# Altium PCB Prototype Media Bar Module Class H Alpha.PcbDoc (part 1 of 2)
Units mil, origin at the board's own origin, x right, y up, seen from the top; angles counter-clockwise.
Board outline 436.13 x 1831.8 mil, 6 copper layers (Component Side, Ground Plane (GND), Inner Layer 1, Inner Layer 2, Power Plane (VCC), Solder Side), stack 51.068 mil thick; 139 components, 72 nets, 710 pads, 418 vias.
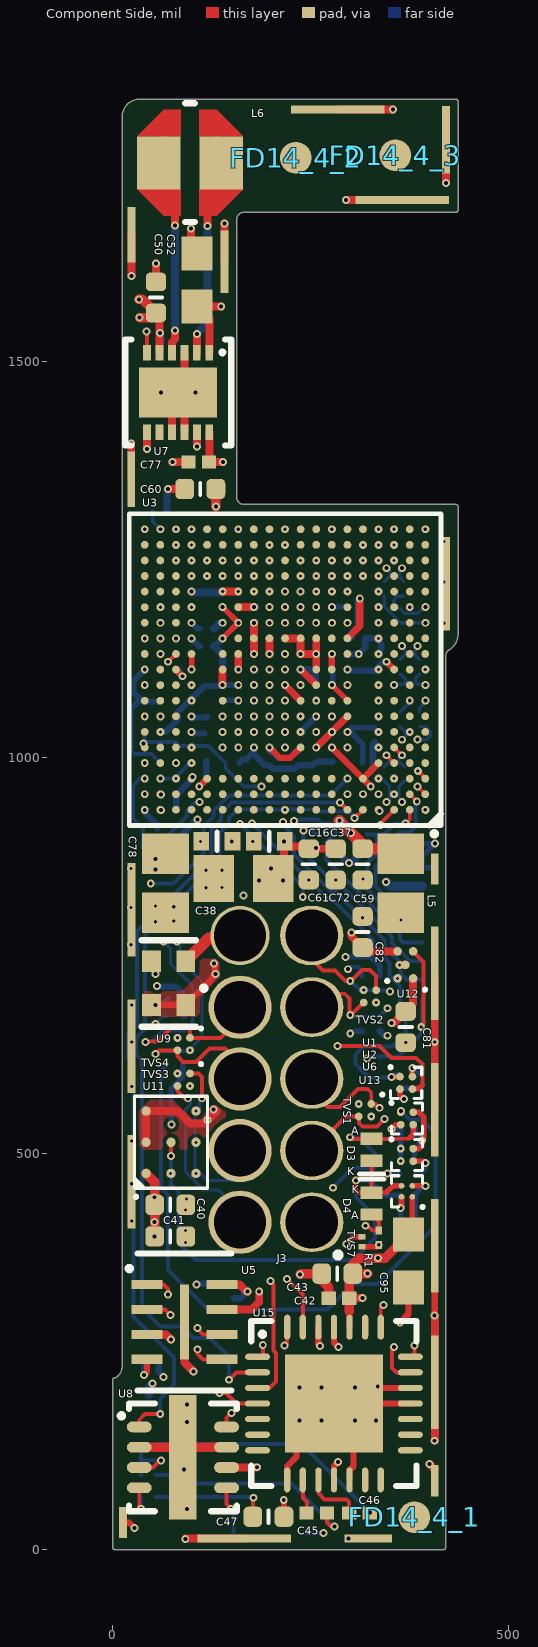
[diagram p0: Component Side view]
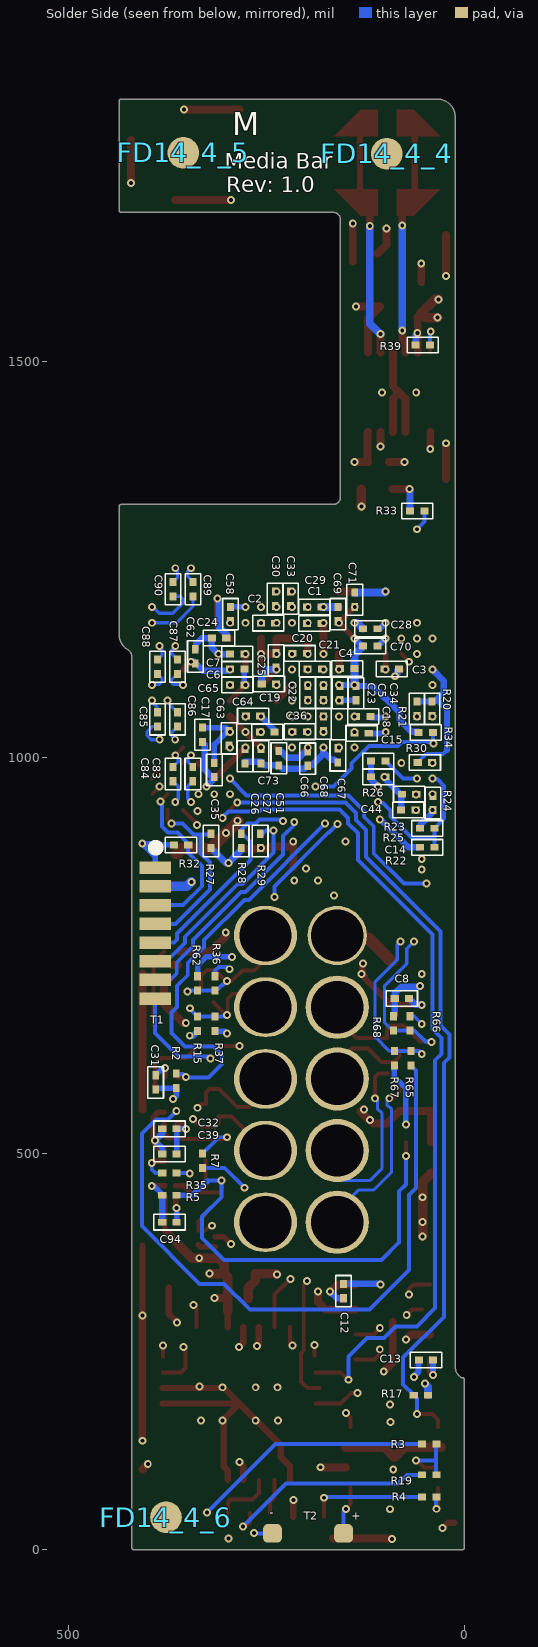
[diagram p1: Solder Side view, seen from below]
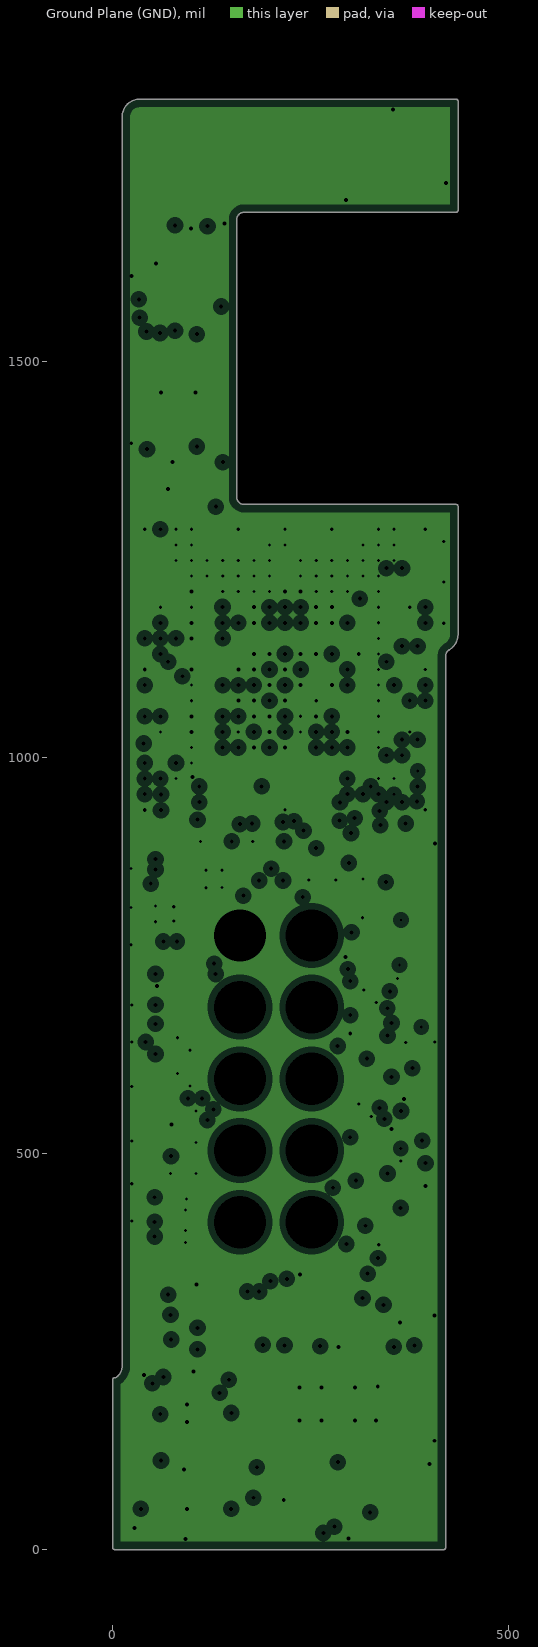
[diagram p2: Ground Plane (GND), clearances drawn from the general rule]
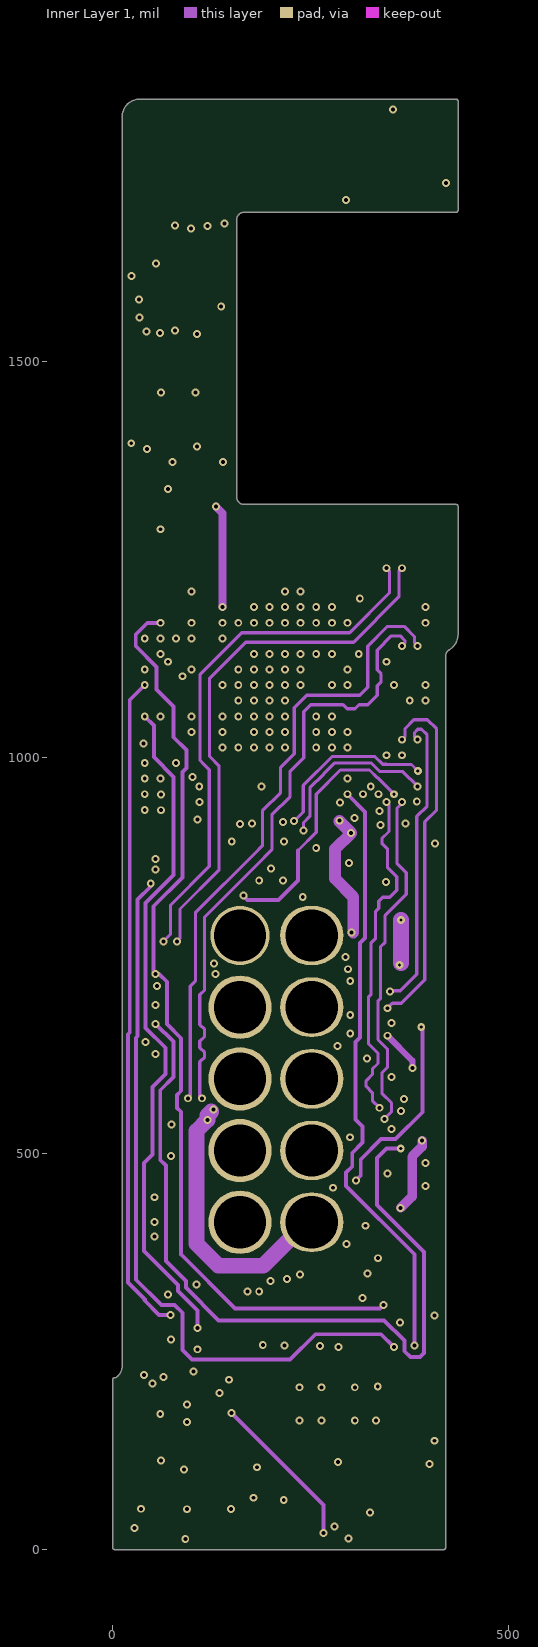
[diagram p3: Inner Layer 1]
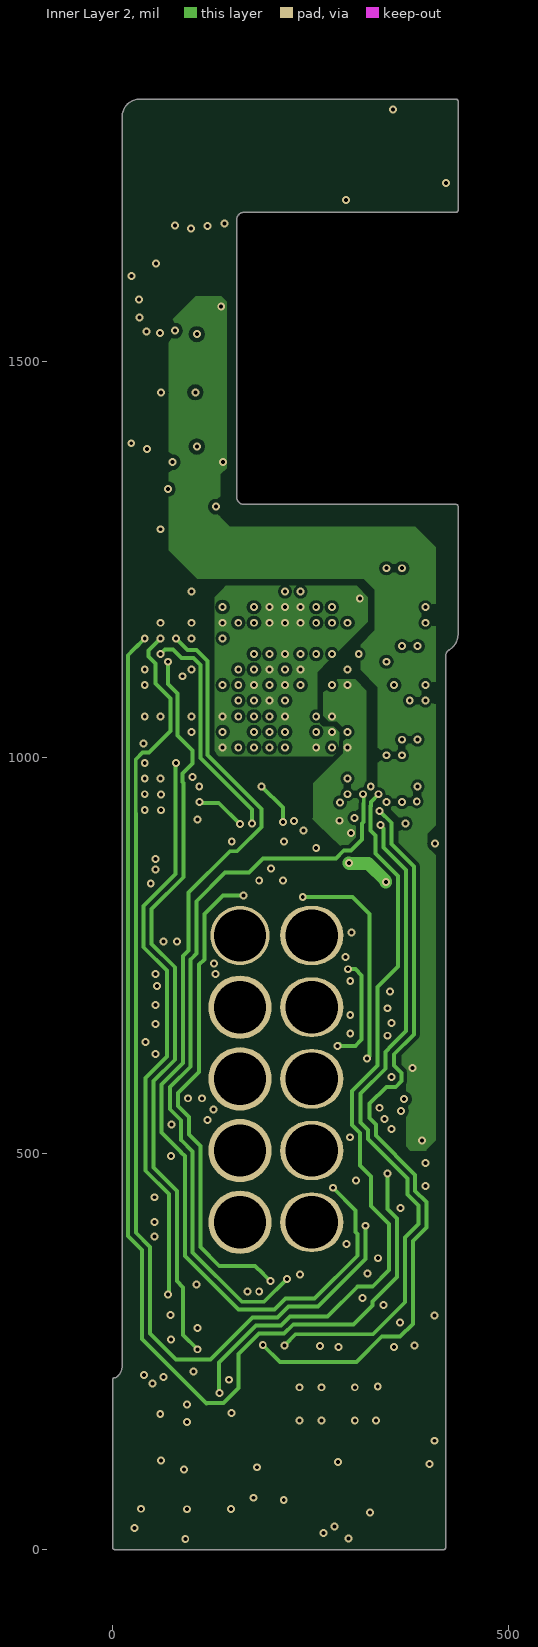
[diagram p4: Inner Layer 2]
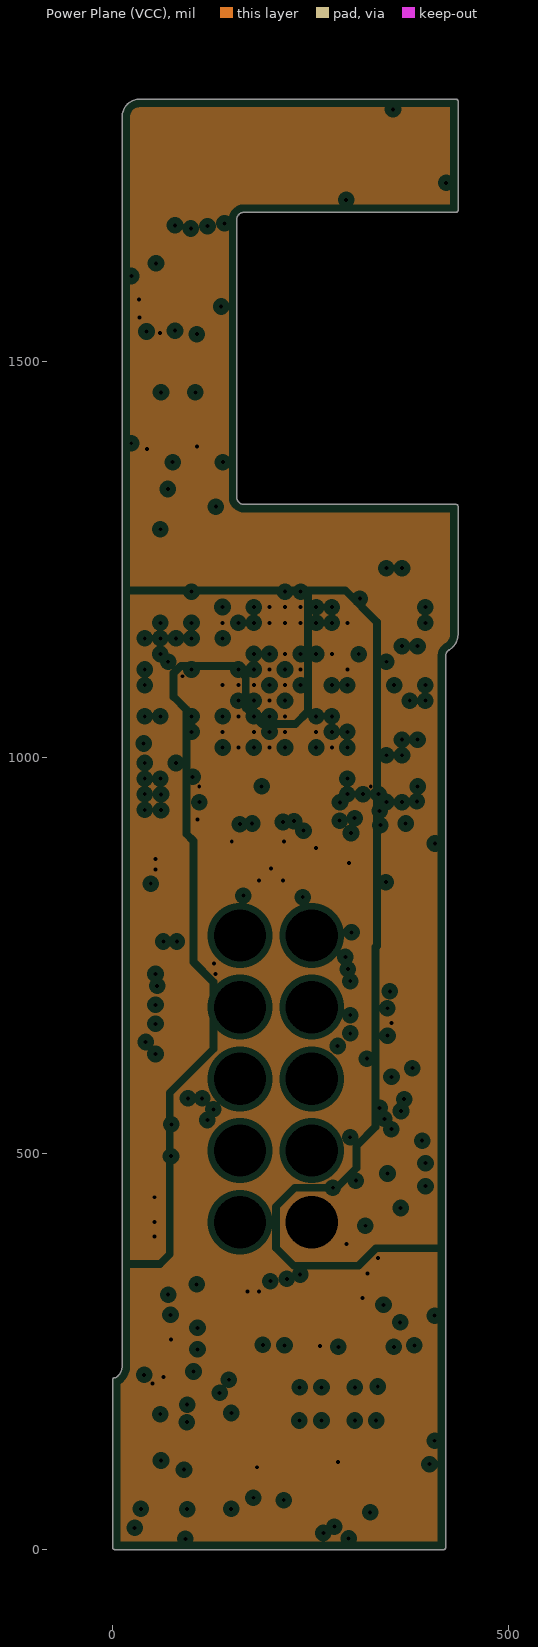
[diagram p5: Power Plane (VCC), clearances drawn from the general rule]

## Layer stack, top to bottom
Top Solder: solder mask 0.4, Solder Resist, Dk 3.5
Component Side: signal copper 1.4
Dielectric1: core 12.6, FR-4, Dk 4.8
Ground Plane (GND): plane copper 1.417, net GND
Dielectric4: prepreg 5, Dk 4.2
Inner Layer 1: signal copper 1.417
Dielectric2: core 10, Dk 4.2
Inner Layer 2: signal copper 1.417
Dielectric3: prepreg 5, Dk 4.2
Power Plane (VCC): plane copper 1.417, net (Multiple Nets)
Dielectric5: core 10, Dk 4.2
Solder Side: signal copper 1.4
Bottom Solder: solder mask 0.4, Solder Resist, Dk 3.5

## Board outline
0,2.51 ccw(c2.51,2.51) 2.51,0 417.87,0 ccw(c417.87,2.51) 420.38,2.51 420.38,1128.38 cw(c429.68,1128.38) 425.03,1136.44 ccw(c413.93,1155.66) 436.13,1155.66 436.13,1317.48 ccw(c433.62,1317.48) 433.62,1319.99 165.9,1319.99 cw(c165.9,1329.29) 156.6,1329.29 156.6,1679.68 cw(c165.9,1679.68) 165.9,1688.98 ccw(c165.9,1691.49) 165.92,1688.98 433.62,1688.98 ccw(c433.62,1691.49) 436.13,1691.49 436.13,1829.29 ccw(c433.62,1829.29) 433.62,1831.8 34.01,1831.8 cw(c34.01,1829.29) 34.03,1831.8 34.01,1831.8 ccw(c34.01,1809.6) 11.81,1809.6 11.81,231.63 cw(c-5.36,231.63) 3.47,216.91 ccw(c2.51,214.59) 0,214.59

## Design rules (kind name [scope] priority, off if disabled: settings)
Clearance Clearance_1 [withinroom(U3)] p1: gap=3.9
Clearance diff_1 [InNetClass('diff')] p2: gap=5
Clearance [All] p3: gap=5
DiffPairsRouting [All] p1: maxlimit=8 minlimit=8 mostfreqgap=8 toplayer_minwidth=15 toplayer_maxwidth=15 toplayer_prefwidth=15 midlayer1_minwidth=15 midlayer1_maxwidth=15 midlayer1_prefwidth=15 midlayer2_minwidth=15 midlayer2_maxwidth=15 midlayer2_prefwidth=15 bottomlayer_minwidth=15 bottomlayer_maxwidth=15 bottomlayer_prefwidth=15 maxuncoupledlength=500
FabricationTestPointUsage [All] p1 off: valid=0 allowmultiple=FALSE
FabricationTestpoint [(IsPad And (OnTopLayer Or OnBottomLayer))] p1 off: side=3 testpointundercomponent=TRUE minsize=40 maxsize=100 preferedsize=60 minholesize=0 maxholesize=40 preferedholesize=32 testpointgrid=1 allowsidetop=TRUE allowsidebottom=TRUE usegrid=TRUE gridtolerance=0.01
HoleToHoleClearance [All] p1: gap=3.9 allowstackedmicrovias=TRUE
MinimumSolderMaskSliver [All] p1: minsoldermaskwidth=3
PlaneClearance [All] p1: clearance=8
PlaneConnect [All] p1: planeconnectstyle=Direct reliefexpansion=8 reliefentries=4 reliefconductorwidth=8 reliefairgap=8
PolygonConnect [All] p1: connectstyle=Direct reliefconductorwidth=10 reliefentries=4 polygonreliefangle="90 Angle" airgapwidth=10
RoomDefinition U3 [InComponentClass('Components Class 1')] p1: confinementstyle=ConfineIn formatcopy=TRUE lockcomponents=FALSE outline 19,1308 411,1308 411,914 19,914
RoutingVias RoutingVias_1 [All] p1: holewidth=5 width=10 viastyle="Through Hole" minholewidth=4 minwidth=10 maxholewidth=6 maxwidth=12
SilkToSilkClearance [All] p1: silktosilkclearance=3
SilkToSolderMaskClearance [IsPad] p1: minsilkscreentomaskgap=3 clearancetoexposedcopper=TRUE
SolderMaskExpansion [All] p1: expansion=4
Width DiffPair_Width [InAnyDifferentialPair] p1: maxlimit=5 minlimit=4 preferedwidth=4
Width [All] p2: maxlimit=30 minlimit=4 preferedwidth=5
20 further rules are at their usual default settings.

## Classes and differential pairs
component class "Components Class 1": C1 C2 C3 C4 C5 C6 C7 C15 C17 C18 C19 C20 C21 C22 C23 C24 C25 C26 C27 C28 C29 C30 C33 C34 C35 C36 C44 C51 C58 C62 C63 C64 C65 C66 C67 C68 C69 C70 C71 C73 C83 C84 C85 C86 C87 C88 C89 C90 R20 R21 R23 R24 R25 R26 R28 R30 R32 R34
differential pair C_RX_CLK: +C_RX_CLK_P -C_RX_CLK_N
differential pair C_RX: +C_RX_P -C_RX_N
differential pair C_TX_CLK: +C_TX_CLK_P -C_TX_CLK_N
differential pair C_TX: +C_TX_P -C_TX_N
differential pair RX_CLK: +RX_CLK_P -RX_CLK_N
differential pair RX: +RX_P -RX_N
differential pair TX_CLK: +TX_CLK_P -TX_CLK_N
differential pair TX: +TX_P -TX_N

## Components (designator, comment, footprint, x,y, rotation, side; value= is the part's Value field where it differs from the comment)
C1 "0.1uF" C_01005 189.62,1169.49 r0 bottom
C2 "0.1uF" C_01005 248,1170 r180 bottom
C3 "0.1uF" C_01005 92,1112 r180 bottom
C4 "0.1uF" C_01005 148,1113 r180 bottom
C5 "0.1uF" C_01005 157.4,1081.8 r90 bottom
C6 "0.1uF" C_01005 287,1112 r0 bottom
C7 "0.1uF" C_01005 287,1131 r180 bottom
C8 "0.1uF" C_01005 79,696 r180 bottom
C12 "0.1uF" C_01005 152.62,326.49 r90 bottom
C13 "0.1uF" C_01005 48.62,239.49 r180 bottom
C14 "0.1uF" C_01005 47,911 r0 bottom
C15 "0.1uF" C_01005 130,1031 r180 bottom
C16 "1.0uF" C_ERA-0402 131.62,894.49 r0 top
C17 "0.1uF" C_01005 331,1029 r90 bottom
C18 "0.1uF" C_01005 128,1052 r0 bottom
C19 "0.1uF" C_01005 247,1093 r0 bottom
C20 "0.1uF" C_01005 208,1132 r0 bottom
C21 "0.1uF" C_01005 189,1112 r0 bottom
C22 "0.1uF" C_01005 198,1082 r270 bottom
C23 "0.1uF" C_01005 178,1082 r90 bottom
C24 "0.1uF" C_01005 310,1151.1 r180 bottom
C25 "0.1uF" C_01005 238,1123 r270 bottom
C26 "0.1uF" C_01005 277,1002 r90 bottom
C27 "0.1uF" C_01005 257,1002 r90 bottom
C28 "0.1uF" C_01005 119,1163 r0 bottom
C29 "0.1uF" C_01005 189.62,1190.49 r0 bottom
C30 "0.1uF" C_01005 239,1201 r270 bottom
C31 "0.1uF" C_01005 390,590 r90 bottom
C32 "0.1uF" C_01005 372.62,531.49 r0 bottom
C33 "0.1uF" C_01005 219.62,1200.84 r270 bottom
C34 "0.1uF" C_01005 136.8,1081.7 r90 bottom
C35 "0.1uF" C_01005 316,984.6 r270 bottom
C36 "0.1uF" C_01005 208,1033 r0 bottom
C37 "1.0uF" C_ERA-0402 197.62,894.49 r0 top
C38 "22uF" C_ERA-0805 165.12,847.49 r0 top
C39 "0.1uF" C_01005 372.62,499.49 r0 bottom
C40 "10uF" C_0402 72.62,435.49 r180 top
C41 "1uF" C_0402 72.62,395.49 r180 top
C42 "0.01uF" CAPC0201 285.62,317.5 r0 top
C43 "10uF" C_0402 283.62,348.49 r0 top
C44 "0.1uF" C_01005 109,976 r0 bottom
C45 "C_0201_1uF" CAPC0201 257.62,45.99 r180 top
C46 "C_0201_1uF" CAPC0201 311.62,45.99 r180 top
C47 "2.2uF" C_0402 196.62,41.49 r180 top
C50 "10uF" C_0402 54.62,1581.49 r270 top
C51 "0.1uF" C_01005 234.5,999.5 r90 bottom
C52 "22uF" C_ERA-0603 106.62,1603.49 r270 top
C58 "0.1uF" C_01005 295.62,1181.49 r270 bottom
C59 "10uF" C_0402 315.62,865.49 r90 top
C60 "10uF" C_0402 110.62,1339.49 r0 top
C61 "10uF" C_0402 247.62,865.49 r90 top
C62 "0.1uF" C_01005 340,1128 r270 bottom
C63 "0.1uF" C_01005 297.62,1024.49 r270 bottom
C64 "0.1uF" C_01005 267,1053 r0 bottom
C65 "0.1uF" C_01005 287,1092 r0 bottom
C66 "0.1uF" C_01005 198,999 r90 bottom
C67 "0.1uF" C_01005 160,1003 r90 bottom
C68 "0.1uF" C_01005 178,1043 r270 bottom
C69 "0.1uF" C_01005 159.62,1181.49 r270 bottom
C70 "0.1uF" C_01005 119,1141 r0 bottom
C71 "0.1uF" C_01005 138.62,1199.49 r270 bottom
C72 "10uF" C_0402 281.62,865.49 r90 top
C73 "0.1uF" C_01005 249.2,1032.6 r0 bottom
C77 "0.47礔" CAPC0201 108.62,1373.49 r0 top
C78 "22uF" C_ERA-0805 66.62,841.49 r90 top
C81 "4.7uF" C_0402 370,660 r90 top
C82 "10uF" C_0402 315.62,780 r270 top
C83 "0.1uF" C_01005 343.12,979.49 r90 bottom
C84 "0.1uF" C_01005 368.12,979.49 r90 bottom
C85 "0.1uF" C_01005 387.62,1048.49 r90 bottom
C86 "0.1uF" C_01005 362.62,1048.49 r90 bottom
C87 "0.1uF" C_01005 362.62,1115 r270 bottom
C88 "0.1uF" C_01005 387.62,1115 r270 bottom
C89 "0.1uF" C_01005 343,1213 r270 bottom
C90 "0.1uF" C_01005 368,1213 r270 bottom
C94 "0.1uF" C_01005 372.62,413.49 r180 bottom
C95 "22uF" C_ERA-0603 373.62,364.49 r90 top
D3 "SBR0240LP-7" 2-XFDFN 327,505 r90 top
D4 "SBR0240LP-7" 2-XFDFN 327,437 r270 top
FD14_4_1 "FIDUCIAL-1.0" fid 381,41 r0 top
FD14_4_2 "FIDUCIAL-1.0" fid 231,1758 r0 top
FD14_4_3 "FIDUCIAL-1.0" fid 357,1761 r0 top
FD14_4_4 "FIDUCIAL-1.0" fid 98,1763 r180 bottom
FD14_4_5 "FIDUCIAL-1.0" fid 355,1764 r180 bottom
FD14_4_6 "FIDUCIAL-1.0" fid 377,41 r180 bottom
J3 "SPRING PIN" "10PIN SMD CONNECTOR" 251.31,413.43 r90 top
L5 "2.2uH" C_ERA-0805 363.62,841.49 r90 top
L6 "2.2uH Wirewound" L_SMD_2.2uH 97.62,1751.49 r0 top
R1 "10K" R_01005 336,394 r90 top
R2 "10K" R_01005 364,592 r90 bottom
R3 "R_01005_270K" R_01005 44.62,133.49 r180 bottom
R4 "R_01005_130K" R_01005 44.62,66.49 r180 bottom
R5 "10K" R_01005 372.62,447.49 r0 bottom
R7 "10K" R_01005 331,491 r270 bottom
R15 "10K" R_01005 337,664 r270 bottom
R17 "1k" R_01005 55,195 r0 bottom
R19 "R_01005_270K" R_01005 44.62,94.49 r180 bottom
R20 "1k" R_01005 41,1062 r270 bottom
R21 "1k" R_01005 60,1062 r90 bottom
R22 "10K" R_01005 47,887 r180 bottom
R23 "10K" R_01005 70,954 r0 bottom
R24 "10K" R_01005 40,943 r270 bottom
R25 "10K" R_01005 71,934 r0 bottom
R26 "10K" R_01005 109,996 r0 bottom
R27 "4.7k" R_01005 320,895 r90 bottom
R28 "4.7k" R_01005 282,895 r90 bottom
R29 "4.7k" R_01005 258,895 r90 bottom
R30 "10K" R_01005 50,994 r0 bottom
R32 "4.7k" R_01005 358,890 r0 bottom
R33 "10K" R_01005 59.62,1311.49 r0 bottom
R34 "10K" R_01005 49,1032 r0 bottom
R35 "10K" R_01005 372.62,475.49 r180 bottom
R36 "10K" R_01005 315,715 r90 bottom
R37 "1M Ohms" R_01005 315,664 r270 bottom
R39 "10K" R_01005 52.62,1521.49 r180 bottom
R62 "1M Ohms" R_01005 337,715 r90 bottom
R65 "10K" R_01005 67.62,620.49 r270 bottom
R66 "10K" R_01005 68.62,664.49 r90 bottom
R67 "1M Ohms" R_01005 88.62,620.49 r270 bottom
R68 "1M Ohms" R_01005 89.62,664.49 r90 bottom
T1 "8 PIN TEST_INTERFACE" "8-PIN TEST INTERFACE" 390.62,778.49 r180 bottom
T2 "2 PIN TEST" 2pin 197.62,20.49 r270 bottom
TVS1 "Dual TVS" TSLP-4-10 318.62,555 r270 top
TVS2 "Dual TVS" TSLP-4-10 324.84,698.68 r270 top
TVS3 "Dual TVS" TSLP-4-10 89.62,593.49 r270 top
TVS4 "Dual TVS" TSLP-4-10 89.62,638.49 r270 top
TVS7 "TVS_ESDAVLC6-1BV2" ST_MICRO_TVS 315,389 r270 top
U1 "Buffer" DSBGA4_.4MM 370.62,589.49 r270 top
U2 "Buffer" DSBGA4_.4MM 371.62,544.49 r270 top
U3 "LFE3-17EA" BGA328C50P19X19_1000X1000X150 217.62,1111.49 r180 top locked
U5 "M25P16-VMC6TG" UFDFN8 90.62,287.49 r0 top
U6 "Buffer" DSBGA4_.4MM 371.62,498.49 r270 top
U7 "3.3V STEP UP/DOWN" QFN40P300X300X80_HS-13L 82.62,1461.49 r180 top
U8 "IC AMP AUDIO PWR 1.45W MONO 8SON" 8VDFN 88.62,116.49 r0 top
U9 "12MHz Oscillator" LCCS165P160X200X70-4N 70.62,715.49 r90 top
U11 "TPS82675SIPT" "MICRP SIP" 73.62,514.49 r90 top
U12 "2.5V Buck Converter" BGA4C50P2X2_105X138X60 369.62,738.49 r90 top
U13 "Power Switch" DSBGA4 371.62,452.49 r90 top
U15 "Audio Codec" S-PQFP-N28 279.42,184.49 r0 top

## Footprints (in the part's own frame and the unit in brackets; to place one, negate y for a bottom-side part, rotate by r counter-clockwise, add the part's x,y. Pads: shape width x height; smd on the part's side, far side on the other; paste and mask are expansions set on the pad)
2-XFDFN [mm] "2-XFDFN"
  rect 0.4x0.7 smd paste+0 mask+0: 1(0.35,0) 2(-0.35,0)
  silkscreen extent -0.78,-0.38 -0.78,0.4
2pin [mm] "knolwes speaker 2403 260 00086"
  rrect50% 0.6x0.6 smd paste+0 mask+0: 1(0,1.14) 2(0,-1.14)
"8-PIN TEST INTERFACE" [mm] "SOIC, 4-Leads, Body 3.7x6.0mm (max), Pitch 1.27mm, IPC High Density"
  rect 1x0.4 smd paste+0 mask+0: 1(0,2.1) 2(0,1.5) 3(0,0.9) 4(0,0.3) 5(0,-0.3) 6(0,-0.9) 7(0,-2.1) 8(0,-1.5)
  silkscreen extent -0.11,2.62 0.14,2.87
8VDFN [mm] "QFN, 12-Leads, Body 3.00x3.00mm, Pitch 0.65mm, Thermal Pad 2.37x0.88mm, IPC Medium Density"
  oval 0.8x0.35 smd paste+0 mask+0: 1(-1.4,0.975) 2(-1.4,0.325) 3(-1.4,-0.325) 4(-1.4,-0.975) 5(1.4,-0.975) 6(1.4,-0.325) 7(1.4,0.325) 8(1.4,0.975)
  rect 0.88x4 smd paste+0 mask+0: 9(0,0)
  silkscreen extent -2.05,-1.73 1.73,1.73, body extent -1.58,-1.58 1.58,1.58, height 1
"10PIN SMD CONNECTOR" [mil] "10PIN TONKA MODULE CONNECTOR"
  oval 75x80 hole 66 paste+0 mask+0: 1(0,0) 3(90.55,0) 5(181.1,0) 7(271.65,0) 9(362.2,0)
  round 80 hole 66 paste+0 mask+0: 2(0,90.55) 4(90.55,90.55) 6(181.1,90.55) 8(271.65,90.55)
  round 74.8 hole 66 paste+0 mask+0: 10(362.2,90.55)
  silkscreen extent -45,-37 -38,-30, body extent -36,-36 398,127, height 16
BGA4C50P2X2_105X138X60 [mm] "BGA, 4-Leads, Body 1.05x1.38mmx0.60mm, Pitch 0.50mm"
  round 0.275 smd paste+0 mask+0: A1(-0.433,-0.25) A3(-0.433,0.25) B2(0,0) C1(0.433,-0.25) C3(0.433,0.25)
  silkscreen extent -0.84,-0.68 -0.75,-0.58, body extent -0.69,-0.52 0.69,0.53, height 0.6
BGA328C50P19X19_1000X1000X150 [mm] "BGA, 328-Leads, Body 10.00x10.00mmx1.50mm, Pitch 0.50mm"
  round 0.25 smd paste+0 mask+0: A1(-4.5,4.5) A2(-4,4.5) A3(-3.5,4.5) A4(-3,4.5) A5(-2.5,4.5) A6(-2,4.5) A7(-1.5,4.5) A8(-1,4.5) A9(-0.5,4.5) A10(0,4.5) A11(0.5,4.5) A12(1,4.5) A13(1.5,4.5) A14(2,4.5) A15(2.5,4.5) A16(3,4.5) A17(3.5,4.5) A18(4,4.5) A19(4.5,4.5) B1(-4.5,4) B2(-4,4) B3(-3.5,4) B4(-3,4) B5(-2.5,4) B6(-2,4) B7(-1.5,4) B8(-1,4) B9(-0.5,4) B10(0,4) B11(0.5,4) B12(1,4) B13(1.5,4) B14(2,4) B15(2.5,4) B16(3,4) B17(3.5,4) B18(4,4) B19(4.5,4) C1(-4.5,3.5) C2(-4,3.5) C3(-3.5,3.5) C4(-3,3.5) C5(-2.5,3.5) C6(-2,3.5) C7(-1.5,3.5) C8(-1,3.5) C9(-0.5,3.5) C10(0,3.5) C11(0.5,3.5) C12(1,3.5) C13(1.5,3.5) C14(2,3.5) C15(2.5,3.5) C16(3,3.5) C17(3.5,3.5) C18(4,3.5) C19(4.5,3.5) D1(-4.5,3) D2(-4,3) D3(-3.5,3) D4(-3,3) D16(3,3) D17(3.5,3) D18(4,3) D19(4.5,3) E1(-4.5,2.5) E2(-4,2.5) E3(-3.5,2.5) E4(-3,2.5) E6(-2,2.5) E7(-1.5,2.5) E8(-1,2.5) E9(-0.5,2.5) E10(0,2.5) E11(0.5,2.5) E12(1,2.5) E13(1.5,2.5) E14(2,2.5) E16(3,2.5) E17(3.5,2.5) E18(4,2.5) E19(4.5,2.5) F1(-4.5,2) F2(-4,2) F3(-3.5,2) F4(-3,2) F6(-2,2) F7(-1.5,2) F8(-1,2) F9(-0.5,2) F10(0,2) F11(0.5,2) F12(1,2) F13(1.5,2) F14(2,2) F16(3,2) F17(3.5,2) F18(4,2) F19(4.5,2) G1(-4.5,1.5) G2(-4,1.5) G3(-3.5,1.5) G4(-3,1.5) G6(-2,1.5) G7(-1.5,1.5) G8(-1,1.5) G9(-0.5,1.5) G10(0,1.5) G11(0.5,1.5) G12(1,1.5) G13(1.5,1.5) G14(2,1.5) G16(3,1.5) G17(3.5,1.5) G18(4,1.5) G19(4.5,1.5) H1(-4.5,1) H2(-4,1) H3(-3.5,1) H4(-3,1) H6(-2,1) H7(-1.5,1) H8(-1,1) H9(-0.5,1) H10(0,1) H11(0.5,1) H12(1,1) H13(1.5,1) H14(2,1) H16(3,1) H17(3.5,1) H18(4,1) H19(4.5,1) J1(-4.5,0.5) J2(-4,0.5) J3(-3.5,0.5) J4(-3,0.5) J6(-2,0.5) J7(-1.5,0.5) J8(-1,0.5) J9(-0.5,0.5) J10(0,0.5) J11(0.5,0.5) J12(1,0.5) J13(1.5,0.5) J14(2,0.5) J16(3,0.5) J17(3.5,0.5) J18(4,0.5) J19(4.5,0.5) K1(-4.5,0) K2(-4,0) K3(-3.5,0) K4(-3,0) K6(-2,0) K7(-1.5,0) K8(-1,0) K9(-0.5,0) K10(0,0) K11(0.5,0) K12(1,0) K13(1.5,0) K14(2,0) K16(3,0) K17(3.5,0) K18(4,0) K19(4.5,0) L1(-4.5,-0.5) L2(-4,-0.5) L3(-3.5,-0.5) L4(-3,-0.5) L6(-2,-0.5) L7(-1.5,-0.5) L8(-1,-0.5) L9(-0.5,-0.5) L10(0,-0.5) L11(0.5,-0.5) L12(1,-0.5) L13(1.5,-0.5) L14(2,-0.5) L16(3,-0.5) L17(3.5,-0.5) L18(4,-0.5) L19(4.5,-0.5) M1(-4.5,-1) M2(-4,-1) M3(-3.5,-1) M4(-3,-1) M6(-2,-1) M7(-1.5,-1) M8(-1,-1) M9(-0.5,-1) M10(0,-1) M11(0.5,-1) M12(1,-1) M13(1.5,-1) M14(2,-1) M16(3,-1) M17(3.5,-1) M18(4,-1) M19(4.5,-1) N1(-4.5,-1.5) N2(-4,-1.5) N3(-3.5,-1.5) N4(-3,-1.5) N6(-2,-1.5) N7(-1.5,-1.5) N8(-1,-1.5) N9(-0.5,-1.5) N10(0,-1.5) N11(0.5,-1.5) N12(1,-1.5) N13(1.5,-1.5) N14(2,-1.5) N16(3,-1.5) N17(3.5,-1.5) N18(4,-1.5) N19(4.5,-1.5) P1(-4.5,-2) P2(-4,-2) P3(-3.5,-2) P4(-3,-2) P6(-2,-2) P7(-1.5,-2) P8(-1,-2) P9(-0.5,-2) P10(0,-2) P11(0.5,-2) P12(1,-2) P13(1.5,-2) P14(2,-2) P16(3,-2) P17(3.5,-2) P18(4,-2) P19(4.5,-2) R1(-4.5,-2.5) R2(-4,-2.5) R3(-3.5,-2.5) R4(-3,-2.5) R6(-2,-2.5) R7(-1.5,-2.5) R8(-1,-2.5) R9(-0.5,-2.5) R10(0,-2.5) R11(0.5,-2.5) R12(1,-2.5) R13(1.5,-2.5) R14(2,-2.5) R16(3,-2.5) R17(3.5,-2.5) R18(4,-2.5) R19(4.5,-2.5) T1(-4.5,-3) T2(-4,-3) T3(-3.5,-3) T4(-3,-3) T5(-2.5,-3) T6(-2,-3) T7(-1.5,-3) T8(-1,-3) T9(-0.5,-3) T10(0,-3) T11(0.5,-3) T12(1,-3) T13(1.5,-3) T14(2,-3) T15(2.5,-3) T16(3,-3) T17(3.5,-3) T18(4,-3) T19(4.5,-3) U1(-4.5,-3.5) U2(-4,-3.5) U3(-3.5,-3.5) U4(-3,-3.5) U5(-2.5,-3.5) U6(-2,-3.5) U7(-1.5,-3.5) U8(-1,-3.5) U9(-0.5,-3.5) U10(0,-3.5) U11(0.5,-3.5) U12(1,-3.5) U13(1.5,-3.5) U14(2,-3.5) U15(2.5,-3.5) U16(3,-3.5) U17(3.5,-3.5) U18(4,-3.5) U19(4.5,-3.5) V1(-4.5,-4) V2(-4,-4) V3(-3.5,-4) V4(-3,-4) V5(-2.5,-4) V6(-2,-4) V7(-1.5,-4) V8(-1,-4) V9(-0.5,-4) V10(0,-4) V11(0.5,-4) V12(1,-4) V13(1.5,-4) V14(2,-4) V15(2.5,-4) V16(3,-4) V17(3.5,-4) V18(4,-4) V19(4.5,-4) W1(-4.5,-4.5) W2(-4,-4.5) W3(-3.5,-4.5) W4(-3,-4.5) W5(-2.5,-4.5) W6(-2,-4.5) W7(-1.5,-4.5) W8(-1,-4.5) W9(-0.5,-4.5) W10(0,-4.5) W11(0.5,-4.5) W12(1,-4.5) W13(1.5,-4.5) W14(2,-4.5) W15(2.5,-4.5) W16(3,-4.5) W17(3.5,-4.5) W18(4,-4.5) W19(4.5,-4.5)
  silkscreen extent -5,-5 5,5.35, body extent -5,-5 5,5, height 1.5
C_0402 [mm] "Capacitor 0402"
  rrect50% 0.6x0.65 smd paste+0 mask+0: 1(-0.5,0) 2(0.5,0)
  silkscreen extent 0,-0.2 0,0.2, body extent -0.5,-0.3 0.5,0.3, height 0.2
C_01005 [mm] "Chip Capacitor, Body 0.4x0.2mm, Height 0.22mm, IPC High Density"
  rect 0.26x0.22 smd paste+0 mask+0: 1(-0.23,0) 2(0.23,0)
  silkscreen extent -0.5,-0.25 0.5,0.25, body extent -0.21,-0.11 0.21,0.11, height 0.22
C_ERA-0402 [mm]
  rect 0.5x0.6 smd paste+0 mask+0: 1(-0.5,0) 2(0.5,0)
  silkscreen extent 0,-0.3 0,0.3, body extent -0.5,-0.3 0.5,0.3, height 0.2
C_ERA-0603 [mm]
  rect 1.1x1 smd paste+0 mask+0: 1(-0.85,0) 2(0.85,0)
  body extent -0.8,-0.4 0.8,0.4, height 0.3
C_ERA-0805 [mm]
  rect 1.3x1.5 smd paste+0 mask+0: 1(-0.95,0) 2(0.95,0)
  body extent -0.94,-0.63 1.06,0.63, height 0.78
CAPC0201 [mm] "Chip Capacitor, Body 0.6x0.3mm, Height 0.33mm, IPC Medium Density"
  rect 0.46x0.42 smd paste+0 mask+0: 1(-0.33,0) 2(0.33,0)
  body extent -0.31,-0.16 0.32,0.17, height 0.33
DSBGA4 [mm] "BGA, 4-Leads"
  round 0.18 smd paste+0 mask+0.025: A1(-0.175,-0.175) A2(-0.175,0.175) B1(0.175,-0.175) B2(0.175,0.175)
  silkscreen extent -0.55,-0.55 0.5,0.5, body extent -0.33,-0.35 0.35,0.35, height 0.6
DSBGA4_.4MM [mm] "BGA, 4-Leads"
  round 0.25 smd paste+0 mask+0.025: A1(-0.2,-0.2) A2(-0.2,0.2) B1(0.2,-0.2) B2(0.2,0.2)
  silkscreen extent -0.55,-0.55 0.5,0.5, body extent -0.4,-0.4 0.4,0.4, height 0.5
fid [mil]
  round 40 smd paste+0 mask+10: 0(0,0)
L_SMD_2.2uH [mm] "Inductor"
  rect 1.4x1.7 smd paste+0 mask+0: 1(1,0) 2(-1,0)
  Component Side region: 0.3,0.85 0.3,1.7 0.85,1.7 1.7,0.85
  Component Side region: -0.3,0.85 -0.3,1.7 -0.85,1.7 -1.7,0.85
  Component Side region: -0.3,-0.85 -0.3,-1.7 -0.85,-1.7 -1.7,-0.85
  Component Side region: 0.3,-0.85 0.3,-1.7 0.85,-1.7 1.7,-0.85
  silkscreen extent -0.15,-1.9 0.15,1.91, body extent -1.7,-1.7 1.7,1.7, height 1.2
LCCS165P160X200X70-4N [mm]
  rect 0.7x0.6 smd paste+0 mask+0: 1(-0.7,-0.55) 2(0.7,-0.55) 3(0.7,0.55) 4(-0.7,0.55)
  silkscreen extent -1.4,-1.2 1.38,0.87, body extent -1.05,-0.85 1.05,0.85, height 1.2
"MICRP SIP" [mm]
  round 0.3 smd paste+0 mask+0: A1(-1,0.8) A2(0,0.8) A3(1,0.8) B1(-1,0) B2(0,0) C1(-1,-0.8) C2(0,-0.8) C3(1,-0.8)
  silkscreen extent -1.8,-1.17 1.48,1.17, body extent -1.48,-1.17 1.48,1.17, height 1
QFN40P300X300X80_HS-13L [mm] "QFN, 12-Leads, Body 3.00x3.00mm, Pitch 0.40mm, Thermal Pad 2.50x1.60mm, IPC High Density"
  rect 0.25x0.5 smd paste+0 mask+0: 1(-1,-1.275) 2(-0.6,-1.275) 3(-0.2,-1.275) 4(0.2,-1.275) 5(0.6,-1.275) 6(1,-1.275) 7(1,1.275) 8(0.6,1.275) 9(0.2,1.275) 10(-0.2,1.275) 11(-0.6,1.275) 12(-1,1.275)
  rect 2.5x1.6 smd paste+0 mask+0: 13(0,0)
  silkscreen extent -1.7,-1.7 1.7,1.7, body extent -1.5,-1.5 1.5,1.5, height 0.8
R_01005 [mm] "Chip Capacitor, Body 0.4x0.2mm, Height 0.22mm, IPC High Density"
  rect 0.26x0.22 smd paste+0 mask+0: 1(-0.23,0) 2(0.23,0)
  body extent -0.21,-0.11 0.21,0.11, height 0.22
S-PQFP-N28 [mm] "QFN, 28-Leads, Body 5.00x5.00mm, Pitch 0.50mm, Thermal Pad 3.13x3.13mm, IPC Medium Density"
  oval 0.8x0.2 smd paste+0 mask+0: 1(-2.45,1.5) 2(-2.45,1) 3(-2.45,0.5) 4(-2.45,0) 5(-2.45,-0.5) 6(-2.45,-1) 7(-2.45,-1.5) 15(2.45,-1.5) 16(2.45,-1) 17(2.45,-0.5) 18(2.45,0) 19(2.45,0.5) 20(2.45,1) 21(2.45,1.5)
  oval 0.2x0.8 smd paste+0 mask+0: 8(-1.5,-2.45) 9(-1,-2.45) 10(-0.5,-2.45) 11(0,-2.45) 12(0.5,-2.45) 13(1,-2.45) 14(1.5,-2.45) 22(1.5,2.45) 23(1,2.45) 24(0.5,2.45) 25(0,2.45) 26(-0.5,2.45) 27(-1,2.45) 28(-1.5,2.45)
  rect 3.13x3.13 smd paste-3.13 mask+0: 29(0,0)
  silkscreen extent -2.65,-2.65 2.65,2.65, body extent -2.5,-2.5 2.5,2.5, height 0.8
ST_MICRO_TVS [mm] "Chip Capacitor, Body 0.4x0.2mm, Height 0.22mm, IPC High Density"
  rect 0.18x0.225 smd paste+0 mask+0: 1(-0.16,0) 2(0.16,0)
  body extent -0.21,-0.11 0.21,0.11, height 0.22
TSLP-4-10 [mm]
  round 0.25 smd paste+0 mask+0: A1(-0.2,0.2) A2(0.2,0.2) B1(-0.2,-0.2) B2(0.2,-0.2)
  silkscreen extent -0.55,0.51 -0.45,0.6, body extent -0.38,-0.38 0.38,0.38, height 0.4
UFDFN8 [mm]
  rect 1x0.3 smd paste+0 mask+0: 1(-1.2,1.2) 2(-1.2,0.4) 3(-1.2,-0.4) 4(-1.2,-1.2) 5(1.2,-1.2) 6(1.2,-0.4) 7(1.2,0.4) 8(1.2,1.2)
  rect 0.3x2.4 smd paste+0 mask+0: 9(0,0)
  silkscreen extent -1.84,-2.2 1.5,2.2, body extent -1.5,-2 1.5,2, height 0.6

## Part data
C1 C2 C3 C4 C5 C6 C7 C8 C12 C13 C14 C15 C17 C18 C19 C20 C21 C22 C23 C24 C25 C26 C27 C28 C29 C30 C31 C32 C33 C34 C35 C36 C39 C44 C51 C58 C62 C63 C64 C65 C66 C67 C68 C69 C70 C71 C73 C83 C84 C85 C86 C87 C88 C89 C90 C94: library part C_01005_0.1uF, "CAP CER 0.1UF 6.3V 20% X5R 01005"
C16 C37: library part C_0402_1.0UF_16V, "CAP CER 1.0UF 16V X5R 0402"
C38 C78: library part C_0805_22UF_6.3V, "CAP CER 22UF 6.3V X7R 10% 0805"
C40 C43 C50 C59 C60 C61 C72 C82: library part C_0402_10uF, "CAP CER 10UF 4V 20% X5R 0402"
C41: library part C_0402_1uF, "CAP CER 1UF 6.3V 20% JB 0402"
C42: library part C_0201_0.01UF, "CAP CER 10000PF 6.3V X7R 0201"
C45 C46: "1uF 0201 X5R"
C47: library part C_0402_2.2uF, "CAP CER 2.2UF 6.3V X5R 0402"
C52 C95: library part C_0603_22uF, "CAP CER 22UF 6.3V 20% X5R 0603"
C77: library part C_0201_0.47µF, "CAP CER 0.47UF 6.3V 20% JB 0201"
C81: library part C_0402_4.7uF, "CAP CER 4.7UF 6.3V 10% X7R 0603"
D3 D4: library part D_SBR0240LP-7, "DIODE SUP BARRIER 40V 0.25A 2DFN"
J3: library part J_TONKA_MODULE_CONNECTOR
L5: library part L_0805_2.2uH_160mOhm, "INDUCTOR MULTILAYER 2.2UH 0805"
L6: library part L_SMD_2.2uH, "COIL CHOKE 2.2UH SHIELDED SMD"
R1 R2 R5 R7 R15 R22 R23 R24 R25 R26 R30 R33 R34 R35 R36 R39 R65 R66: library part R_01005_10K, "RES 10K OHM 1/32W 1% 01005"
R3 R19: library part R_01005_270K_5%, "RES 270K OHM 1/32W 5% 01005 SMD"
R4: library part R_01005_130K_5%, "RES 130K OHM 1/32W 5% 01005 SMD"
R17 R20 R21: library part R_01005_1k, "RES 1K OHM 1/32W 1% 01005 SM"
R27 R28 R29 R32: library part R_01005_4.7k, "RES 4.7K OHM 1/32W 1% 01005 SMD"
R37 R62 R67 R68: library part R_01005_1M, "RES 1M OHM 1/32W 1% 01005 SMD"
T1: library part TEST_INTERFACE, "8 PIN Test Interface"
T2: library part J_2PIN_PADS, "2 Pin Connector"
TVS1 TVS2 TVS3 TVS4: library part TVS_ESD102U2099ELE6327XTSA1, "TVS DIODE 3.3VWM 11VC TSLP4-10"
TVS7: "Single Line Bi Trans 8pF"
U1 U2 U6: library part U_SN74AUP1G34YFPR, "IC BUFFER GATE SGL 4-DSBGA"
U3: library part U_LFE3-17EA-MG328, "IC FPGA 17KLUTS 116I/O 328-BGA"
U5: library part U_M25P16-VMC6TG, "IC FLASH 16MBIT 75MHZ 8UFDFPN"
U7: library part U_LM3668SD-2833/NOPB, "IC REG BUCK BST SYNC ADJ 12-LLP"
U8: library part TPA2006D1DRBR
U9: library part U_ASA-12.000MHZ-L-T, "OSC 12MHZ 3.3V SMD"
U11: library part U_TPS82675SIPT, "IC REG BUCK SYNC 1.2V 0.6A 8USIP"
U12: library part U_LM3671TL-2.5/NOPB, "IC REG BUCK SYNC 2.5V 0.6A 5USMD"
U13: library part U_FPF1504BUCX, "IC LOAD MGMT SWITCH ADV 4WLCSP"
U15: library part TLV320AIC23B

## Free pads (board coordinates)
  rect 10x39.39 smd paste+0 mask+0: 2(12.74,34.06)
  rect 10x70 smd paste+0 mask+0: 2(23.38,1351.87) 2(23.62,1660.49)
  rect 10x118.11 smd paste+0 mask+0: 2(23.62,464.31) 2(23.62,635.96) 2(23.62,808.01) 2(406.69,211.16) 2(406.69,384) 2(406.69,555.65) 2(406.69,727.7) 2(420.64,1219.86)
  rect 10x78.74 smd paste+0 mask+0: 2(141.1,1626.52)
  rect 118.11x10 smd paste+0 mask+0: 2(165.9,13.93) 2(284.41,1818.88) 2(365.51,1704.7)
  rect 60x10 smd paste+0 mask+0: 2(322.99,13.93)
  rect 10x40 smd paste+0 mask+0: 2(406.69,86.83)
  rect 10x39.37 smd paste+0 mask+0: 2(406.69,859.49)
  rect 10x85 smd paste+0 mask+0: 2(421.02,1780.45)

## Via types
v1: diameter 10, hole 5, Component Side to Solder Side, tented both sides, 279 vias
v2: diameter 10, hole 4, Component Side to Ground Plane (GND), tented both sides, 132 vias
v3: diameter 10, hole 4, Ground Plane (GND) to Inner Layer 1, tented both sides, 6 vias
v4: diameter 10, hole 5, Component Side to Solder Side, 1 vias

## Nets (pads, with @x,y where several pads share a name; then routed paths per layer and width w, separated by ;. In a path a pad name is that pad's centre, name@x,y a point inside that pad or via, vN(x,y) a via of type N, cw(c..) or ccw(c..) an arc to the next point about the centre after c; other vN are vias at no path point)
AMP_SHUTDOWN: R17.2 U3.A6 U8.1 | length 1047.1
  Component Side w5: U8.1@33.5,154.88 33.5,164 40.5,171 v1(60,171) ; v1(287,943.68) U3.A6@296.36,934.33
  Solder Side w5: v1(60,171) 60,190.94 R17.2@64.06,195 ; R17.2@64.06,195 77.5,208.5 77.5,242.49 26,293.99 26,614.86 19.09,621.76 19.09,650.37 30.5,661.78 30.5,780.8 124.61,874.9 124.61,909.04 137,921.44 137,930.41 150.28,943.69 286.69,943.69 v1@287,944
BAT+: C50.2 C81.2 J3.1 R39.1 TVS7.1 U7.5 U7.7 U7.11 U11.A2 U11.A3 U12.A1 | length 761.7
  Component Side w7: v1(295,386) 304.3,395.3 TVS7.1@315,395.3 ; 305.19,395.24 TVS7.1@312.96,395.24
  Component Side w8: C50.2@54.62,1561.81 C50.2@59.62,1556.81
  Component Side w10: U11.A2@42.12,514.49 U11.A3@42.12,553.86 82.19,553.86 98.1,537.96 114.96,537.96 v1(119.57,542.57) 122,545 123,545 131.29,553.29 127.79,556.79 v1(127,556) ; v1(43.25,1389.86) U7.7@43.25,1411.3 ; U7.5@59,1511.69 59,1556.19 C50.2@59.62,1556.81 ; v1(106.24,1393.11) U7.11@106.24,1411.3 ; v1(352,665) 355.31,665 C81.2@370,679.69 379.46,689.15 379.46,710 U12.A1@379.46,721.45
  Component Side w12: v1(33,1579) 37.42,1579 C50.2@54.62,1561.81 ; v1(34,1556) 48.81,1556 C50.2@54.62,1561.81 ; C50.2@53.55,1560.74 C50.2@54.62,1561.81
  Inner Layer 1 w20: v1@124.4,553.12 119.57,548.29 v1(119.57,542.57) 105.76,528.76 105.76,386.24 133.57,358.43 190.15,358.43 245.15,413.43 J3.1@251.31,413.43
  Solder Side w8: R39.1@61.67,1521.49 v1@61.67,1534.44
  other v1: 59.62,1536.49
C_RX_CLK_N: C90.1 J3.6 R65.1 R67.1 TVS4.B2 | length 1053.8
  Component Side w5: v1(54,626) 58.62,630.62 TVS4.B2@81.74,630.62 81.74,623.26 89,616 105,616 122,633 142,633 160.76,614.24 J3.6@160.76,594.54
  Inner Layer 1 w4: v1(81,768) 85,772 85,809.03 134,858.03 134,990 123,1001 ; 122.41,1001.56 122.41,1100.44 167.97,1146 304.2,1146 361.41,1203.22 361.41,1235.6 v1(365.26,1239.45)
  Solder Side w4: v1(81,768) 85,764 85,745 112.95,717.05 112.95,647.7 94.8,629.55 R67.1@88.62,629.55 ; v1(365.26,1239.45) 362.26,1236.45 362.26,1227.8 C90.1@368,1222.06
  Solder Side w5: v1(54,626) 57.55,629.55 R65.1@67.62,629.55 R67.1@88.62,629.55
C_RX_CLK_P: C89.1 J3.8 R66.1 R68.1 TVS4.A1 | length 1054.6
  Component Side w5: v1(41.59,641.05) 42.04,641.5 56.5,641.5 77,662 94,662 97.86,658.14 97.86,646 136.37,646 ; 136.37,646.37 160.76,670.76 J3.8@160.76,685.09
  Inner Layer 1 w4: v1(64,768) 73,777 73,814 122,863 122,985 113.01,993.99 110.41,996.62 110.41,1105.41 163,1158 299.23,1158 349.41,1208.19 349.41,1235.6 v1(345.57,1239.45)
  Solder Side w4: v1(64,768) 73,759 73,740.03 100.95,712.08 100.95,665.53 R68.1@90.86,655.44 ; C89.1@342.93,1222.48 350.26,1229.8 350.26,1234.76 v1(345.57,1239.45)
  Solder Side w5: v1(41.59,641.05) 42.04,641.5 49.5,641.5 63.44,655.44 R66.1@68.62,655.44 R68.1@89.62,655.44
C_RX_N: C88.1 J3.2 TVS3.B2 | length 1036.5
  Component Side w5: TVS3.B2@81.74,585.62 81.74,579.26 91,570 v1(95,570)
  Inner Layer 1 w4: v1(95,570) 98,573 98,711.64 104.36,718 104.36,804.3 179.03,878.97 ; 179.03,879.03 189,889 189,932.97 212.03,956 212.03,987.94 229.18,1005.09 229.18,1063.18 245,1079 312,1079 322,1089 322,1141 347,1166 368.07,1166 381.1,1152.97 381.1,1144.86 v1(384.94,1141.02)
  Solder Side w4: v1(95,570) 98,567 98,561.86 92.05,555.92 92.05,476.85 114.91,454 134,454 160.76,427.24 J3.2@160.76,413.43 ; v1(384.94,1141.02) 381.94,1138.02 381.94,1129.73 C88.1@387.62,1124.06
C_RX_P: C87.1 J3.4 TVS3.A1 | length 1033.3
  Component Side w5: TVS3.A1@97.49,601.37 108.63,601.37 113,597 v1(113,570)
  Inner Layer 1 w4: v1(113,570) 110,573 110,616 116,622 116,628 110,634 110,642 116,648 116,657 110,663 110,700.79 116,706.79 116,798.97 191.03,874 191.03,874.06 191.96,874.99 ; 192.01,874.99 191.96,874.99 ; v1(365.26,1141.02) 369.1,1144.86 369.1,1148 363.1,1154 351.97,1154 334,1136.03 334,1111 339,1106 339,1096 334,1091 334,1079 322,1067 311,1067 306,1062 296,1062 291,1067 249.97,1067 241.18,1058.21 241.18,1000.12 224.03,982.97 224.03,951.03 201,928 201,884.03 191.99,875.01
  Solder Side w4: v1(113,570) 110,567 110,556.89 104.05,550.94 104.05,481.82 119.88,466 153,466 166,479 166,498.75 J3.4@160.76,503.99 ; C87.1@362.62,1124.06 369.94,1131.38 369.94,1136.34 v1(365.26,1141.02)
C_TX_CLK_N: C86.1 J3.7 R15.1 R37.1 TVS2.B2 | length 620.9
  Component Side w5: J3.7@251.31,685.09 262.09,685.09 279,702 293,702 299,696 299,685 v1@299,676 ; v1@302.16,676 305.58,679.42 310.58,684.42 TVS2.B2@316.97,690.81
  Inner Layer 1 w4: v1(346.84,683.68) 353.16,690 364.46,690 394,719.54 394,919.03 409,934.03 409,1036.46 397.46,1048 380.33,1048 369.3,1036.97 369.3,1026.82 v1(365.34,1022.85)
  Solder Side w4: C86.1@362.62,1039.44 369.3,1032.75 369.3,1026.63 369.11,1026.63 v1(365.34,1022.85)
  Solder Side w5: v1(300,675) 301.94,673.06 R37.1@315,673.06 R15.1@337,673.06 v1@346.84,682.9
C_TX_CLK_P: C85.1 J3.9 R36.1 R62.1 TVS2.A1 | length 624.3
  Component Side w5: J3.9@251.31,775.64 251.31,745.69 265.5,731.5 280.5,731.5 294,718 v1(300,718) 301,718 315,732 325,732 332.72,724.28 TVS2.A1@332.72,706.56
  Inner Layer 1 w4: v1(350,705) 350.8,705.8 363.29,705.8 384,726.51 384,926 397,939 397,1029 390,1036 385.3,1036 381.3,1032 381.3,1026.55 v1(384.93,1022.92)
  Solder Side w4: v1@385.11,1022.74 395.74,1022.74 401,1028 401,1033 394.56,1039.44 C85.1@387.62,1039.44
  Solder Side w5: v1(300,718) 305,713 306,713 313.05,705.94 R36.1@315,705.94 R62.1@337,705.94 v1@349.06,705.94
C_TX_N: C84.1 J3.3 TVS1.B2 | length 606.2
  Component Side w5: J3.3@251.31,503.99 294.45,547.13 TVS1.B2@310.74,547.13 310.74,539 315.12,534.63 333.63,534.63 v1(343,544)
  Inner Layer 1 w4: v1(343,544) 352,553 352,558 ; 352,562.03 352,558 ; v1(365.32,944.1) 365.42,944 365.42,942.48 358.94,935.99 358.94,866.65 370.62,854.97 370.62,827.62 344,801 344,767 338,761 338,695.79 334.84,692.64 334.84,649 335,648.84 335,644.03 347,632.03 347,608.97 340,601.97 340,576.21 352,564.21 352,558
  Solder Side w4: 361.62,954.84 361.62,963.94 ; v1(365.32,944.1) 361.62,947.81 361.62,963.94 ; C84.1@368.12,970.44 361.62,963.94
C_TX_P: C83.1 J3.5 TVS1.A1 | length 605.1
  Component Side w5: J3.5@251.31,594.54 251.31,579.69 272,559 287,559 310,582 322,582 326.49,577.51 TVS1.A1@326.49,562.87 332.13,562.87 v1(337,558)
  Inner Layer 1 w4: v1(337,558) 328,567 328,577 320,585 320,592 328,600 328,606.94 335,613.94 335,627.06 322.84,639.22 322.84,697.61 326,700.76 326,765.97 332,771.97 332,805.97 336.01,809.99 336.01,819.01 340.99,823.99 350.01,823.99 358.62,832.59 358.62,850 346.94,861.68 346.94,885.18 340,892.11 340,898.06 348.9,906.96 348.9,940.87 v1(345.65,944.11)
  Solder Side w4: C83.1@343.12,970.44 349.62,963.94 349.62,948.08 v1(345.65,944.11)
CLK_12MHZ: U3.N18 U9.3 U15.22 | length 1191.2
  Component Side w5: U15.22@338.47,280.95 v1@338.47,305.47
  Inner Layer 1 w5: v1(54,727) 51.5,729.5 51.5,812.5 88.11,849.11 88.11,982.11 93,987 93,1010 77,1026 77,1065 55.5,1086.5 55.5,1114.5 29.05,1140.95 29.05,1155.58 44.02,1170.55 v1(60.14,1170.55) ; v1@58.68,727 68.5,717.18 68.5,663.64 86.5,645.64 86.5,579.5 81,574 81,558 86.5,552.5 86.5,372.5 154.47,304.53 337.53,304.53 v1(342,309)
DETECT_RX: R35.2 U3.M19 | length 1511.8
  Inner Layer 2 w5: 32.29,1142.7 26.43,1136.84 ; v1(40.45,1150.86) 26.43,1136.84 ; v1@346.5,474.5 v1(347,475) 347,430.43 359,418.43 359,344.34 328,313.34 328,308.53 303.97,284.5 228,284.5 216.55,273.05 184.95,273.05 159.12,247.21 159.12,204.11 140,184.99 118.99,184.99 118.57,184.57 110.14,193 110,193 37,266 37,378.19 19.09,396.1 19.09,1129.5 26.43,1136.84
  Solder Side w5: v1@347.49,475.49 R35.2@363.56,475.49
DONE: R34.1 T1.8 U3.E19 | length 533.8
  Inner Layer 2 w5: v1(188.09,963.99) 215,937.08 v1(215,919)
  Solder Side w5: v1(39,1018) v1@39.94,1018.94 ; R34.1@39.94,1033 v1@39.94,1018.94 ; v1(188.09,963.99) 165.45,963.99 142.72,986.72 142.72,993.1 120.88,1014.94 84.06,1014.94 79,1020 41,1020 v1@39.94,1018.94 ; v1(215,919) 215,915 229,901 229,878.14 276.5,830.64 282.19,830.64 342.96,769.87 342.96,762.03 363.43,741.56 363.43,727.69 371.68,719.44 T1.8@390.62,719.44
EXO_DETECT_RX: R66.2 U6.A1 | length 1034.1
  Inner Layer 1 w5: v1(54,664) 76.5,641.5 76.5,596.64 60,580.14 60,492 67,485 67,364.43 92.43,339 92.43,330.8 133.73,289.5 342.82,289.5 368.37,263.95 368.37,250.5 375.87,243 388,243 393.37,248.37 393.37,375.63 382.5,386.5 334,435 334,494.37 346,506.37 v2(363.74,506.37)
  Solder Side w4: v1(54,664) 55.01,665.01 63.55,673.55 R66.2@68.62,673.55
  other v3: 363.74,506.37
EXO_WAKE_RX: R65.2 U2.A1 | length 839
  Solder Side w5: R65.2@67.62,611.44 61.12,604.94 61.12,456.88 70,448 70,353.23 120.24,302.99 271,302.99 303.51,335.5 334.5,335.5 407.5,408.5 407.5,478.36 407.5,525.72 389.78,543.44 374.56,543.44 v1(364,554)
EXO_WAKE_TX: R36.2 U1.B2 | length 322.3
  Component Side w5: v1(284,636) 337,636 352,621 383.17,621 390.99,613.18 390.99,586.63
  Component Side w7: U1.B2@380.8,582 386.37,582 390.99,586.63
  Inner Layer 2 w5: v1@286.5,638.5 v1(284,636) 306.32,636 314.34,644.02 314.34,725 306.34,733 v1(297,733)
  Solder Side w5: v1(297,733) 299.97,735.97 310.2,735.97 315,731.18 R36.2@315,724.06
